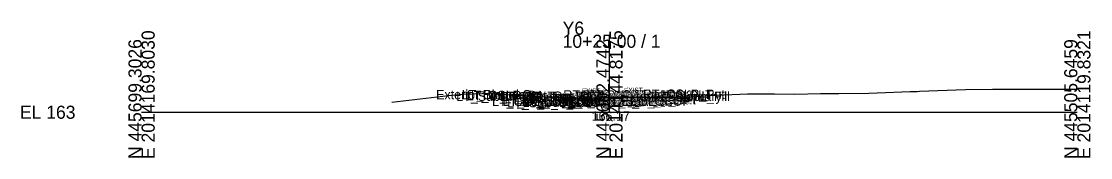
# Model space of a CAD drawing. Extents: x -26 to 203, y -10 to 4529.
# Drawn here: x -25.7 to 202.8, y 490.3 to 519.4 of the extents above; entities that cross this region are included whole.
import ezdxf

# ---------------------------------------------------------------- set-up
doc = ezdxf.new("R2010")
doc.units = 0
for name, color, linetype in [('Default', 7, 'Continuous'), ('Exist Cross Section Cell', 7, 'Continuous'), ('Exist XS Center Line Elevation Label', 7, 'Continuous'), ('Exist XS Ground Line', 7, 'Continuous'), ('Prop XS SE Text', 7, 'Continuous'), ('Scratch_Level_0', 7, 'Continuous')]:
    doc.layers.add(name, color=color, linetype=linetype)

msp = doc.modelspace()

# ---------------------------------------------------------------- linework, layer by layer
at = {"layer": 'Exist Cross Section Cell'}
for p, q in [((100, 500), (100, 516.55)), ((0, 500), (100, 500)), ((100, 500), (200, 500))]:
    msp.add_line(p, q, dxfattribs=at)
at = {"layer": 'Exist XS Ground Line'}
msp.add_lwpolyline([(53.5, 502.13), (65.58, 503.54), (68.82, 503.82), (72.78, 503.98), (75.12, 504.15), (77.86, 503.8), (91.34, 503), (94.01, 503.06), (100, 503.17), (101.11, 503.19), (110.45, 503.24), (114.67, 503.2), (117.53, 503.31), (121.35, 503.55), (122.88, 503.65), (129.48, 503.92), (135.31, 503.91), (139.64, 503.86), (145.09, 503.97), (149.02, 504.01), (155.41, 504.06), (157.23, 504.14), (164.25, 504.39), (165.74, 504.45), (166.26, 504.47), (176.07, 504.85), (181.86, 504.91), (186.4, 504.9), (194.1, 504.93), (196.73, 504.92), (198.28, 504.94), (200, 504.93)], dxfattribs=at)

# ---------------------------------------------------------------- texts
at = {"layer": 'Default'}
msp.add_text('-', height=0.0001, dxfattribs=at).set_placement((0, 500))
at = {"layer": 'Exist Cross Section Cell'}
for s, p in [('Y6', (90, 516.55)), ('10+25.00 / 1', (90, 513.75)), ('EL 163', (-26, 498.6))]:
    msp.add_text(s, height=2.8, dxfattribs=at).set_placement(p)
for s, p in [('E 2014169.8030', (2.8, 490)), ('E 2014144.8175', (102.8, 490)), ('E 2014119.8321', (202.8, 490)), ('N 445699.3026', (0, 490)), ('N 445602.4742', (100, 490)), ('N 445505.6459', (200, 490))]:
    msp.add_text(s, height=2.8, rotation=90, dxfattribs=at).set_placement(p)
at = {"layer": 'Exist XS Center Line Elevation Label'}
msp.add_text('166.17', height=2, dxfattribs=at).set_placement((96.18, 498.17))
at = {"layer": 'Prop XS SE Text'}
for rotation, p in [(1.1458, (94.08, 504.05)), (0.5729, (103.12, 504.2))]:
    msp.add_text('EXIST', height=1, rotation=rotation, dxfattribs=at).set_placement(p)
at = {"layer": 'Scratch_Level_0'}
for s, p in [('Exterior Boundary', (62.94, 502.75)), ('LT_Sub_Trench_Out_DLT', (67.24, 502.42)), ('LT_Slope_Cut', (68.43, 502.75)), ('LT_CSLP_Pnt', (69.51, 502.57)), ('LT_CG1_Shelf_Out', (74.89, 501.35)), ('LT_CG_Top_Face', (76.6, 502.38)), ('LT_CG_Top_BOC', (77.12, 502.38)), ('LT_CG_Bot_BOC', (77.15, 501.36)), ('LT_CG_Top_Gut', (77.57, 501.88)), ('LT_Sub_OEOP', (78.15, 501.06)), ('LT_CG_Bot_IE', (81.25, 501.41)), ('LT_Sub_OEOT', (81.42, 501.12)), ('LT_PV2_OEOT', (81.51, 501.75)), ('LT_PV3_OEOT', (81.51, 501.5)), ('LT_PV1_OEOT', (82.08, 502)), ('RT_Sub_OEEOP', (89.17, 501.3)), ('LT_Sub_OEEOP', (89.21, 501.3)), ('RT_PV2_OEEOP', (89.26, 501.92)), ('RT_PV3_OEEOP', (89.26, 501.67)), ('LT_PV2_OEEOP', (89.31, 501.92)), ('LT_PV3_OEEOP', (89.31, 501.67)), ('RT_PV1_OEEOP', (89.83, 502.05)), ('LT_PV1_OEEOP', (89.87, 502.05)), ('RT_PV2_IEEOP', (89.91, 501.92)), ('LT_PV2_IEEOP', (89.95, 501.92)), ('RT_Sub_Trench_Out_DLT', (90.13, 502.7)), ('RT_PV1_IEEOP', (90.47, 502.05)), ('LT_PV1_IEEOP', (90.52, 502.05)), ('PV2_PGL', (93.91, 501.92)), ('RT_CG_Top_Face', (94.21, 502.66)), ('PV1_PGL', (94.47, 502.17)), ('RT_CG1_Shelf_Out', (94.5, 501.67)), ('RT_CG_Bot_IE', (94.87, 501.64)), ('RT_Sub_OEOT', (95.03, 501.35)), ('RT_PV2_OEOT', (95.13, 501.97)), ('RT_PV3_OEOT', (95.13, 501.72)), ('RT_CG_Top_Gut', (95.19, 502.16)), ('RT_PV1_OEOT', (95.69, 502.22)), ('RT_CG_Top_BOC', (95.74, 502.66)), ('RT_CG_Bot_BOC', (95.77, 501.66)), ('RT_Sub_OEOP', (98.35, 501.38)), ('Exterior Boundary', (102.59, 502.37)), ('RT_CSLP_Pnt', (107.13, 502.85)), ('RT_Slope_Fill', (108.93, 502.37))]:
    msp.add_text(s, height=2, dxfattribs=at).set_placement(p)

doc.saveas('drawing.dxf')
